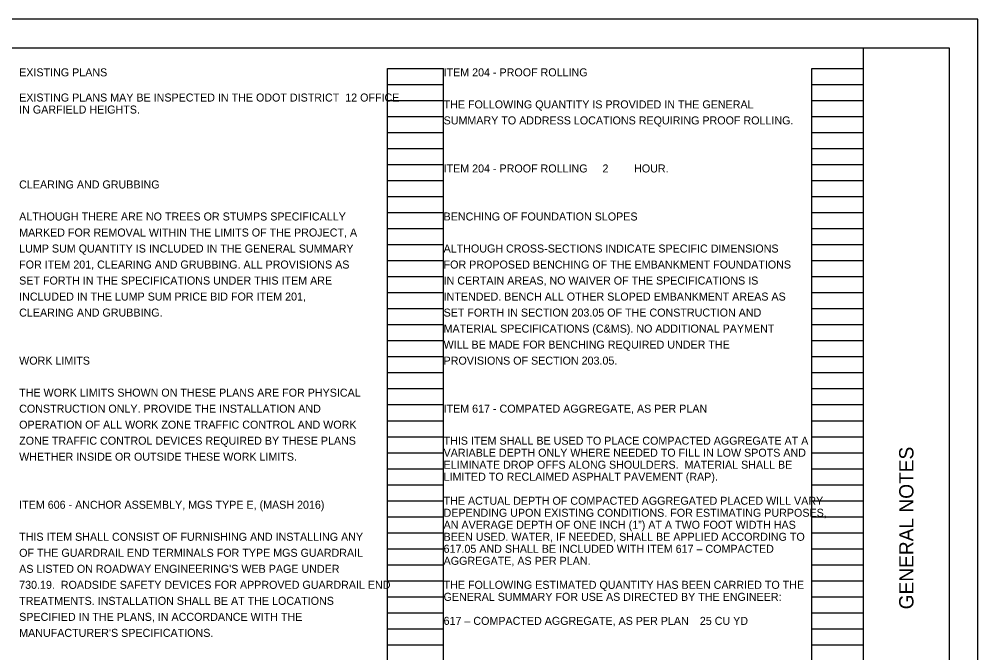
# Model space of a CAD drawing. Extents: x -5.3 to 69.2, y -33.8 to 22.
# Drawn here: x 17.24 to 34, y 10.92 to 22 of the extents above; entities that cross this region are included whole.
import ezdxf

# ---------------------------------------------------------------- set-up
doc = ezdxf.new("R2010")
doc.units = 0
for name, color, linetype in [('SH_Border', 7, 'Continuous'), ('SH_Cut_Line', 7, 'Continuous'), ('SH_Data', 7, 'Continuous'), ('SH_Text', 7, 'Continuous')]:
    doc.layers.add(name, color=color, linetype=linetype)

msp = doc.modelspace()

# ---------------------------------------------------------------- linework, layer by layer
at = {"layer": 'SH_Border'}
msp.add_line((32, 0.5), (32, 21.5), dxfattribs=at)
msp.add_lwpolyline([(1.5, 21.5), (33.5, 21.5), (33.5, 0.5), (1.5, 0.5)], close=True, dxfattribs=at)
at = {"layer": 'SH_Cut_Line'}
msp.add_lwpolyline([(0, 0), (34, 0), (34, 22), (0, 22)], close=True, dxfattribs=at)
at = {"layer": 'SH_Data'}
for p, q in [((23.68, 0.98), (23.68, 21.14)), ((23.68, 21.14), (24.66, 21.14)), ((24.66, 0.98), (24.66, 21.14)), ((31.1, 0.98), (31.1, 21.14)), ((31.1, 21.14), (32, 21.14)), ((32, 0.98), (32, 21.14)), ((23.68, 20.86), (24.66, 20.86)), ((31.1, 20.86), (32, 20.86)), ((23.68, 20.58), (24.66, 20.58)), ((31.1, 20.58), (32, 20.58)), ((23.68, 20.3), (24.66, 20.3)), ((31.1, 20.3), (32, 20.3)), ((23.68, 20.02), (24.66, 20.02)), ((31.1, 20.02), (32, 20.02)), ((23.68, 19.74), (24.66, 19.74)), ((31.1, 19.74), (32, 19.74)), ((23.68, 19.46), (24.66, 19.46)), ((31.1, 19.46), (32, 19.46)), ((23.68, 19.18), (24.66, 19.18)), ((31.1, 19.18), (32, 19.18)), ((23.68, 18.9), (24.66, 18.9)), ((31.1, 18.9), (32, 18.9)), ((23.68, 18.62), (24.66, 18.62)), ((31.1, 18.62), (32, 18.62)), ((23.68, 18.34), (24.66, 18.34)), ((31.1, 18.34), (32, 18.34)), ((23.68, 18.06), (24.66, 18.06)), ((31.1, 18.06), (32, 18.06)), ((23.68, 17.78), (24.66, 17.78)), ((31.1, 17.78), (32, 17.78)), ((23.68, 17.5), (24.66, 17.5)), ((31.1, 17.5), (32, 17.5)), ((23.68, 17.22), (24.66, 17.22)), ((31.1, 17.22), (32, 17.22)), ((23.68, 16.94), (24.66, 16.94)), ((31.1, 16.94), (32, 16.94)), ((23.68, 16.66), (24.66, 16.66)), ((31.1, 16.66), (32, 16.66)), ((23.68, 16.38), (24.66, 16.38)), ((31.1, 16.38), (32, 16.38)), ((23.68, 16.1), (24.66, 16.1)), ((31.1, 16.1), (32, 16.1)), ((23.68, 15.82), (24.66, 15.82)), ((31.1, 15.82), (32, 15.82)), ((23.68, 15.54), (24.66, 15.54)), ((31.1, 15.54), (32, 15.54)), ((23.68, 15.26), (24.66, 15.26)), ((31.1, 15.26), (32, 15.26)), ((23.68, 14.98), (24.66, 14.98)), ((31.1, 14.98), (32, 14.98)), ((23.68, 14.7), (24.66, 14.7)), ((31.1, 14.7), (32, 14.7)), ((23.68, 14.42), (24.66, 14.42)), ((31.1, 14.42), (32, 14.42)), ((23.68, 14.14), (24.66, 14.14)), ((31.1, 14.14), (32, 14.14)), ((23.68, 13.86), (24.66, 13.86)), ((31.1, 13.86), (32, 13.86)), ((23.68, 13.58), (24.66, 13.58)), ((31.1, 13.58), (32, 13.58)), ((23.68, 13.3), (24.66, 13.3)), ((31.1, 13.3), (32, 13.3)), ((23.68, 13.02), (24.66, 13.02)), ((31.1, 13.02), (32, 13.02)), ((23.68, 12.74), (24.66, 12.74)), ((31.1, 12.74), (32, 12.74)), ((23.68, 12.46), (24.66, 12.46)), ((31.1, 12.46), (32, 12.46)), ((23.68, 12.18), (24.66, 12.18)), ((31.1, 12.18), (32, 12.18)), ((23.68, 11.9), (24.66, 11.9)), ((31.1, 11.9), (32, 11.9)), ((23.68, 11.62), (24.66, 11.62)), ((31.1, 11.62), (32, 11.62)), ((23.68, 11.34), (24.66, 11.34)), ((31.1, 11.34), (32, 11.34)), ((23.68, 11.06), (24.66, 11.06)), ((31.1, 11.06), (32, 11.06))]:
    msp.add_line(p, q, dxfattribs=at)

# ---------------------------------------------------------------- texts
msp.add_text('GENERAL NOTES', height=0.25, rotation=90, dxfattribs=at).set_placement((32.875, 11.682))
at = {"layer": 'SH_Text'}
for s, p in [('EXISTING PLANS', (17.24, 21)), ('ITEM 204 - PROOF ROLLING', (24.66, 21)), ('EXISTING PLANS MAY BE INSPECTED IN THE ODOT DISTRICT  12 OFFICE ', (17.24, 20.56)), ('IN GARFIELD HEIGHTS.', (17.24, 20.35)), ('THE FOLLOWING QUANTITY IS PROVIDED IN THE GENERAL', (24.66, 20.44)), ('SUMMARY TO ADDRESS LOCATIONS REQUIRING PROOF ROLLING.', (24.66, 20.16)), ('ITEM 204 - PROOF ROLLING ', (24.66, 19.32)), ('     2       ', (27.178, 19.32)), ('  HOUR.', (27.887, 19.32)), ('CLEARING AND GRUBBING', (17.24, 19.04)), ('ALTHOUGH THERE ARE NO TREES OR STUMPS SPECIFICALLY', (17.24, 18.48)), ('BENCHING OF FOUNDATION SLOPES', (24.66, 18.48)), ('MARKED FOR REMOVAL WITHIN THE LIMITS OF THE PROJECT, A', (17.24, 18.2)), ('LUMP SUM QUANTITY IS INCLUDED IN THE GENERAL SUMMARY', (17.24, 17.92)), ('ALTHOUGH CROSS-SECTIONS INDICATE SPECIFIC DIMENSIONS', (24.66, 17.92)), ('FOR ITEM 201, CLEARING AND GRUBBING. ALL PROVISIONS AS', (17.24, 17.64)), ('FOR PROPOSED BENCHING OF THE EMBANKMENT FOUNDATIONS', (24.66, 17.64)), ('SET FORTH IN THE SPECIFICATIONS UNDER THIS ITEM ARE', (17.24, 17.36)), ('IN CERTAIN AREAS, NO WAIVER OF THE SPECIFICATIONS IS', (24.66, 17.36)), ('INCLUDED IN THE LUMP SUM PRICE BID FOR ITEM 201,', (17.24, 17.08)), ('INTENDED. BENCH ALL OTHER SLOPED EMBANKMENT AREAS AS', (24.66, 17.08)), ('CLEARING AND GRUBBING.', (17.24, 16.8)), ('SET FORTH IN SECTION 203.05 OF THE CONSTRUCTION AND', (24.66, 16.8)), ('MATERIAL SPECIFICATIONS (C&MS). NO ADDITIONAL PAYMENT', (24.66, 16.52)), ('WILL BE MADE FOR BENCHING REQUIRED UNDER THE', (24.66, 16.24)), ('WORK LIMITS', (17.24, 15.96)), ('PROVISIONS OF SECTION 203.05.', (24.66, 15.96)), ('THE WORK LIMITS SHOWN ON THESE PLANS ARE FOR PHYSICAL', (17.24, 15.4)), ('CONSTRUCTION ONLY. PROVIDE THE INSTALLATION AND', (17.24, 15.12)), ('ITEM 617 - COMPATED AGGREGATE, AS PER PLAN', (24.66, 15.12)), ('OPERATION OF ALL WORK ZONE TRAFFIC CONTROL AND WORK', (17.24, 14.84)), ('ZONE TRAFFIC CONTROL DEVICES REQUIRED BY THESE PLANS', (17.24, 14.56)), ('THIS ITEM SHALL BE USED TO PLACE COMPACTED AGGREGATE AT A ', (24.66, 14.56)), ('WHETHER INSIDE OR OUTSIDE THESE WORK LIMITS.', (17.24, 14.28)), ('VARIABLE DEPTH ONLY WHERE NEEDED TO FILL IN LOW SPOTS AND ', (24.66, 14.35)), ('ELIMINATE DROP OFFS ALONG SHOULDERS.  MATERIAL SHALL BE ', (24.66, 14.14)), ('LIMITED TO RECLAIMED ASPHALT PAVEMENT (RAP).', (24.66, 13.93)), ('ITEM 606 - ANCHOR ASSEMBLY, MGS TYPE E, (MASH 2016)', (17.24, 13.44)), ('THE ACTUAL DEPTH OF COMPACTED AGGREGATED PLACED WILL VARY ', (24.66, 13.51)), ('DEPENDING UPON EXISTING CONDITIONS. FOR ESTIMATING PURPOSES, ', (24.66, 13.3)), ('AN AVERAGE DEPTH OF ONE INCH (1”) AT A TWO FOOT WIDTH HAS ', (24.66, 13.09)), ('THIS ITEM SHALL CONSIST OF FURNISHING AND INSTALLING ANY', (17.24, 12.88)), ('BEEN USED. WATER, IF NEEDED, SHALL BE APPLIED ACCORDING TO ', (24.66, 12.88)), ('OF THE GUARDRAIL END TERMINALS FOR TYPE MGS GUARDRAIL', (17.24, 12.6)), ('617.05 AND SHALL BE INCLUDED WITH ITEM 617 – COMPACTED ', (24.66, 12.67)), ('AGGREGATE, AS PER PLAN.', (24.66, 12.46)), ("AS LISTED ON ROADWAY ENGINEERING'S WEB PAGE UNDER", (17.24, 12.32)), ('730.19.  ROADSIDE SAFETY DEVICES FOR APPROVED GUARDRAIL END', (17.24, 12.04)), ('THE FOLLOWING ESTIMATED QUANTITY HAS BEEN CARRIED TO THE ', (24.66, 12.04)), ('TREATMENTS. INSTALLATION SHALL BE AT THE LOCATIONS', (17.24, 11.76)), ('GENERAL SUMMARY FOR USE AS DIRECTED BY THE ENGINEER:', (24.66, 11.83)), ('SPECIFIED IN THE PLANS, IN ACCORDANCE WITH THE', (17.24, 11.48)), ('617 – COMPACTED AGGREGATE, AS PER PLAN', (24.66, 11.41)), ('25 CU YD', (29.14, 11.41)), ("MANUFACTURER'S SPECIFICATIONS.", (17.24, 11.2))]:
    msp.add_text(s, height=0.14, dxfattribs=at).set_placement(p)

doc.saveas('drawing.dxf')
